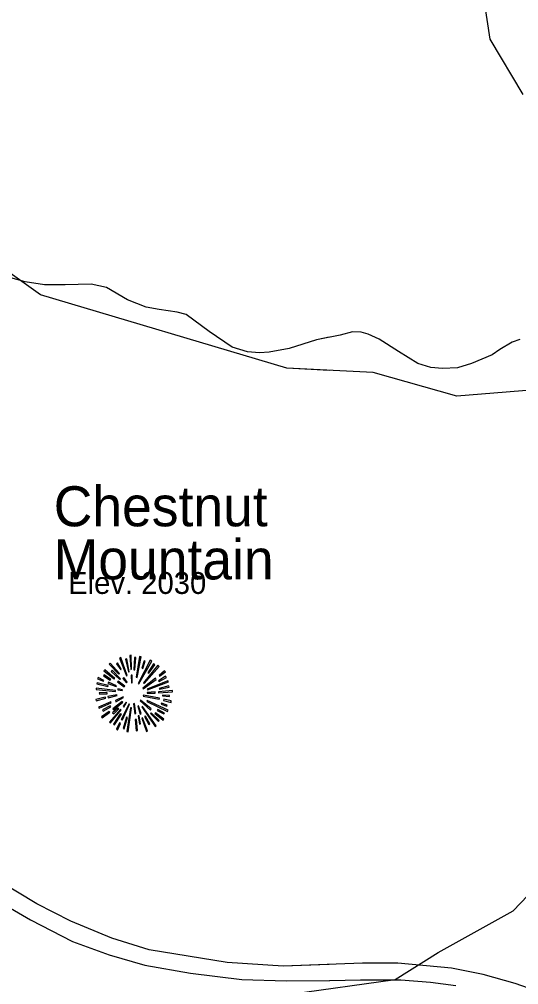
# Model space of a CAD drawing. Extents: x 990631 to 1056237, y 535999 to 585651.
# Drawn here: x 1020086 to 1021960, y 561988 to 565608 of the extents above; entities that cross this region are included whole.
import ezdxf

# ---------------------------------------------------------------- set-up
doc = ezdxf.new("R2010")
doc.units = 0
for name, color, linetype in [('Exist Geographical Mountain Summit CELL', 7, 'Continuous'), ('Exist Geographical Mountain Summit Label', 7, 'Continuous'), ('Exist Hydrographic Creek Single Shore', 7, 'Continuous'), ('Exist Road Non-System Type 51', 7, 'Continuous'), ('Exist Road Primary Interstate Divided Center Attributed', 7, 'Continuous'), ('Exist Survey Geodetic Marker Label', 7, 'Continuous')]:
    doc.layers.add(name, color=color, linetype=linetype)

msp = doc.modelspace()

# ---------------------------------------------------------------- linework, layer by layer
at = {"layer": 'Exist Geographical Mountain Summit CELL'}
for points in [[(1020461.6, 563213), (1020487.8, 563146.1), (1020490.8, 563147.1), (1020466.8, 563215.5)], [(1020500.2, 563222.4), (1020504.2, 563170.4), (1020507.5, 563170.8), (1020506.1, 563223.5)], [(1020516.2, 563168.3), (1020520.1, 563168.3), (1020523.8, 563215.5), (1020518.3, 563215.5)], [(1020528.2, 563139.9), (1020543.1, 563217), (1020537.6, 563218.8), (1020524.9, 563140.7)], [(1020423.1, 563189.7), (1020459.1, 563152.3), (1020462.4, 563154.8), (1020427.2, 563194.4)], [(1020450.7, 563191.2), (1020466.4, 563169.4), (1020468.2, 563170.8), (1020454.8, 563195.2)], [(1020495.5, 563161), (1020498, 563161.7), (1020488.9, 563209.7), (1020484.6, 563208.6)], [(1020531.4, 563118.1), (1020534.4, 563116.3), (1020583, 563200.9), (1020577.6, 563204.6)], [(1020545.9, 563175.1), (1020549.3, 563174), (1020558.7, 563200.9), (1020554, 563202.7)], [(1020552.5, 563119.6), (1020554.7, 563117.4), (1020610.3, 563181.7), (1020606.3, 563186.4)], [(1020590, 563191.2), (1020568.9, 563157.7), (1020571.8, 563156.6), (1020594.3, 563187.9)], [(1020379.9, 563135.2), (1020402.4, 563126.5), (1020403.5, 563129.4), (1020381.4, 563140.3)], [(1020401.7, 563146.1), (1020427.5, 563129.7), (1020429.7, 563132.3), (1020404.6, 563150.1)], [(1020402.8, 563165), (1020442.4, 563134.5), (1020444.6, 563136.7), (1020406.4, 563169.4)], [(1020431.1, 563162), (1020463.8, 563133), (1020466, 563135.2), (1020434, 563167.2)], [(1020474.4, 563136.7), (1020488.2, 563120.2), (1020490.4, 563122.4), (1020477.7, 563139.6)], [(1020505.7, 563149), (1020507.1, 563119.9), (1020509.7, 563120.2), (1020509.7, 563149.4)], [(1020610.3, 563124.7), (1020637.9, 563139.6), (1020635, 563144.6), (1020608.9, 563127.2)], [(1020610.3, 563147.5), (1020612.1, 563145), (1020635, 563161.3), (1020631.4, 563165)], [(1020377, 563115.9), (1020418.4, 563106.5), (1020419.5, 563109.7), (1020378.1, 563120.6)], [(1020418.4, 563118.1), (1020448.9, 563106.1), (1020450.1, 563108.3), (1020420.6, 563122.2)], [(1020454.8, 563123.6), (1020479.9, 563104.6), (1020482, 563107.5), (1020457.3, 563126.8)], [(1020549.3, 563099.6), (1020551.1, 563097), (1020599.7, 563133), (1020596.5, 563137.4)], [(1020566.3, 563096.7), (1020567.4, 563094.4), (1020645.5, 563123.2), (1020643.7, 563127.9)], [(1020612.1, 563096.7), (1020648.9, 563103.2), (1020647.4, 563108.7), (1020610.7, 563098.9)], [(1020374.4, 563094.8), (1020446.4, 563087.9), (1020446.7, 563090.8), (1020374.4, 563099.9)], [(1020386.5, 563077.4), (1020416.2, 563078.9), (1020416.2, 563082.5), (1020385.4, 563082.5)], [(1020418.8, 563068.4), (1020419.9, 563063.6), (1020453, 563072), (1020452.3, 563075.6)], [(1020446.4, 563054.2), (1020448.6, 563049.4), (1020477.3, 563064.6), (1020476.3, 563068)], [(1020455.1, 563093.8), (1020472.2, 563091.6), (1020472.6, 563093.8), (1020455.9, 563098.1)], [(1020550.7, 563070.2), (1020611.4, 563058.2), (1020612.5, 563062.5), (1020551.8, 563073.8)], [(1020565.3, 563084), (1020565.3, 563081.1), (1020595.4, 563081.1), (1020596.1, 563086.1)], [(1020608.5, 563082.9), (1020660.8, 563086.1), (1020661.2, 563090.8), (1020608.9, 563086.1)], [(1020623.4, 563070.9), (1020649.9, 563068.7), (1020649.9, 563073), (1020623.8, 563074.1)], [(1020373, 563057.1), (1020374.4, 563052), (1020410.5, 563062.5), (1020408.3, 563065.8)], [(1020382.8, 563029.4), (1020385.4, 563024.8), (1020430.8, 563044.7), (1020429.3, 563049.4)], [(1020400.3, 563013.5), (1020429.3, 563030.2), (1020427.2, 563033.8), (1020398.1, 563018.5)], [(1020436.6, 563022.9), (1020439.5, 563019.2), (1020474, 563047.6), (1020472.2, 563050.1)], [(1020468.2, 562982.9), (1020472.6, 562981.1), (1020499.1, 563039.6), (1020496.6, 563040.4)], [(1020475.1, 563032.3), (1020478.4, 563029.4), (1020488.5, 563045.8), (1020486.7, 563047.2)], [(1020515.1, 563041.5), (1020519.1, 563004.4), (1020523.5, 563004.7), (1020518.3, 563042.2)], [(1020531.1, 563032.7), (1020539.8, 563002.9), (1020543.8, 563004.7), (1020533.2, 563033.8)], [(1020539.5, 563053.1), (1020578, 563017.8), (1020580.5, 563022.2), (1020541.3, 563055.3)], [(1020545.6, 563030.5), (1020596.1, 562955.7), (1020599.7, 562958.6), (1020548.1, 563031.6)], [(1020564.5, 563050.6), (1020642.7, 563012.3), (1020644.5, 563017.8), (1020566, 563053.4)], [(1020617.9, 563040.4), (1020639, 563032.3), (1020640.8, 563036.7), (1020619.4, 563043.6)], [(1020627.4, 563053.8), (1020655.7, 563046.5), (1020656.4, 563052), (1020628.4, 563058.2)], [(1020394.1, 562992.7), (1020397, 562988.7), (1020425.4, 563009.8), (1020422.7, 563013.1)], [(1020425, 562973.1), (1020427.9, 562970.6), (1020468.6, 563018.2), (1020465.7, 563020.3)], [(1020440.3, 563004.4), (1020459.5, 563022.5), (1020456.2, 563024.8), (1020435.8, 563007.6)], [(1020465, 563004.4), (1020439.9, 562965.1), (1020443.1, 562962.6), (1020469, 563002.2)], [(1020489.6, 562937.5), (1020494.4, 562936.4), (1020507.1, 563025.8), (1020503.8, 563026.6)], [(1020540.9, 562966.2), (1020535.4, 562996), (1020532.2, 562996), (1020536.6, 562965.1)], [(1020556.1, 562993.4), (1020572.1, 562964), (1020576.2, 562966.2), (1020559.8, 562994.9)], [(1020578, 563004.7), (1020608.1, 562975.6), (1020611.4, 562978.2), (1020580.2, 563007.2)], [(1020594.7, 563005.4), (1020625.2, 562979.6), (1020628.4, 562983.3), (1020596.5, 563008)], [(1020603.8, 563016.4), (1020628.8, 563003.3), (1020631.4, 563006.9), (1020606, 563020.3)], [(1020450.1, 562945.9), (1020454.8, 562943), (1020465.7, 562967.6), (1020462.4, 562969.9)], [(1020479.9, 562947.7), (1020491.8, 562990.5), (1020488.2, 562990.9), (1020475.5, 562948.7)], [(1020521.3, 562982.9), (1020524.9, 562940.5), (1020528.9, 562941.5), (1020525.6, 562982.9)], [(1020545.6, 562987.7), (1020563.1, 562937.9), (1020567.4, 562939.7), (1020548.5, 562988.4)]]:
    msp.add_lwpolyline(points, close=True, dxfattribs=at)
at = {"layer": 'Exist Hydrographic Creek Single Shore'}
for points in [[(1021249.1, 564291.9), (1021089.6, 564300), (1020164.9, 564574.6), (1020042.6, 564662.4), (1019938.8, 564799.1), (1019766.4, 564878), (1019451, 564923.8), (1019312.9, 565034.9), (1019245.3, 565256.1), (1019174.5, 565382.3)], [(1022431.1, 563514.8), (1022258.1, 563836.6), (1022232.3, 564053.8), (1022186.8, 564189.2), (1022112.9, 564226.8), (1021728.3, 564195.2), (1021414.4, 564283.6), (1021089.6, 564300), (1020164.9, 564574.6), (1020042.6, 564662.4), (1019938.8, 564799.1), (1019766.4, 564878), (1019451, 564923.8), (1019312.9, 565034.9), (1019245.3, 565256.1), (1019174.5, 565382.3)], [(1021657.7, 562109.2), (1021939, 562264.4), (1022129.1, 562464.1), (1022341.3, 562574.6), (1022478.8, 562703.2), (1022535.1, 562885.8), (1022502.3, 563152.3), (1022435.1, 563390), (1022431.1, 563514.8)], [(1021421.8, 559650), (1021225.3, 559708.5), (1021036.9, 559847.4), (1020643.1, 560042.4), (1020579.7, 560283.3), (1020545, 560494), (1020518.2, 560698.1), (1020521.6, 560796.4), (1020649.1, 561125.4), (1020689.8, 561593.8), (1020761.1, 561730.2), (1020958.5, 561900.2), (1021102.2, 561953.1), (1021495.9, 562007.5), (1021657.7, 562109.2)]]:
    msp.add_lwpolyline(points, dxfattribs=at)
at = {"layer": 'Exist Road Non-System Type 51'}
for points in [[(1022008.3, 566910.7), (1021909.2, 566753.7), (1021900.9, 566563.7), (1021810.1, 566390.2), (1021669.7, 566233.2), (1021686.2, 566158.8), (1021818.3, 565756.4), (1021851.4, 565533.3), (1021975.3, 565326.7)], [(1021249.1, 564415.8), (1021201.7, 564406.7), (1021098.4, 564374.2), (1021024, 564360.7), (1020987.9, 564357.8), (1020941.9, 564361.3), (1020884.5, 564379.3), (1020798.4, 564438.2), (1020712.5, 564501.2), (1020678.9, 564510.3), (1020611, 564520.5), (1020561.4, 564528.3), (1020492.1, 564556.5), (1020413.6, 564603.1), (1020356.1, 564615), (1020258, 564612.4), (1020180, 564613), (1020108.2, 564623.4), (1020054.7, 564639.1)], [(1021964.2, 564407.3), (1021936, 564398.1), (1021889, 564369.6), (1021860.2, 564350.6), (1021783.1, 564317.2), (1021730.6, 564301), (1021674.3, 564298.9), (1021630.6, 564302.2), (1021581.1, 564318), (1021508.3, 564362.5), (1021435.8, 564409), (1021394.6, 564428.2), (1021368.8, 564435.1), (1021336.8, 564436.2), (1021290.3, 564423.7), (1021201.7, 564406.7), (1021098.4, 564374.2), (1021024, 564360.7), (1020987.9, 564357.8), (1020941.9, 564361.3), (1020884.5, 564379.3), (1020798.4, 564438.2), (1020712.5, 564501.2), (1020678.9, 564510.3), (1020611, 564520.5), (1020561.4, 564528.3), (1020492.1, 564556.5), (1020413.6, 564603.1), (1020356.1, 564615), (1020258, 564612.4), (1020180, 564613), (1020108.2, 564623.4), (1020054.7, 564639.1)]]:
    msp.add_lwpolyline(points, dxfattribs=at)
at = {"layer": 'Exist Road Primary Interstate Divided Center Attributed'}
for points in [[(1021249.1, 562063.8), (1021075.9, 562057.6), (1020865.6, 562071), (1020573.6, 562119.2), (1020432.9, 562162.1), (1020278.9, 562226.5), (1020151.6, 562290.8), (1019998.9, 562381.9), (1019605.1, 562635.2), (1019318.5, 562825.5), (1018970.2, 563064), (1018711.7, 563220.8), (1018589.8, 563279.7), (1018481.3, 563318.6), (1018296.5, 563370.9), (1018103.6, 563405.7), (1017977.7, 563420.4), (1017792.8, 563424.5), (1017632.1, 563417.8)], [(1022167.6, 561915.6), (1021946.6, 561991.9), (1021826, 562026.8), (1021708.1, 562049.6), (1021505.9, 562068.3), (1021373.3, 562068.3), (1021075.9, 562057.6), (1020865.6, 562071), (1020573.6, 562119.2), (1020432.9, 562162.1), (1020278.9, 562226.5), (1020151.6, 562290.8), (1019998.9, 562381.9), (1019605.1, 562635.2), (1019318.5, 562825.5), (1018970.2, 563064), (1018711.7, 563220.8), (1018589.8, 563279.7), (1018481.3, 563318.6), (1018296.5, 563370.9), (1018103.6, 563405.7), (1017977.7, 563420.4), (1017792.8, 563424.5), (1017632.1, 563417.8)], [(1017622.7, 563358.8), (1017721.8, 563364.2), (1017926.8, 563364.2), (1018050, 563358.8), (1018201.3, 563336), (1018362.1, 563299.8), (1018508.1, 563246.2), (1018662.1, 563183.3), (1018919.3, 563029.1), (1019287.7, 562781.2), (1019564.9, 562596.3), (1019699.1, 562503.1), (1019968.1, 562324.3), (1020127.5, 562231.8), (1020285.6, 562150.1), (1020423.6, 562100.5), (1020557.5, 562061.6), (1020729, 562030.8), (1020920.5, 562008), (1021087.9, 562002.7), (1021249.1, 562004)], [(1019968.1, 562324.3), (1020127.5, 562231.8), (1020285.6, 562150.1), (1020423.6, 562100.5), (1020557.5, 562061.6), (1020729, 562030.8), (1020920.5, 562008), (1021087.9, 562002.7), (1021251.4, 562004), (1021366.6, 562006.7), (1021517.9, 562006.7), (1021629.1, 561997.3), (1021724.2, 561985.2)]]:
    msp.add_lwpolyline(points, dxfattribs=at)

# ---------------------------------------------------------------- texts
at = {"layer": 'Exist Geographical Mountain Summit Label'}
for s, p in [('Chestnut', (1020215.2, 563707.1)), ('Chestnut', (1020215.2, 563707.1)), ('Mountain', (1020215.2, 563507.9)), ('Mountain', (1020215.2, 563507.9))]:
    msp.add_text(s, height=150, dxfattribs=at).set_placement(p)
at = {"layer": 'Exist Survey Geodetic Marker Label'}
msp.add_text('Elev. 2030', height=82.02, dxfattribs=at).set_placement((1020269.2, 563453.4))

doc.saveas('drawing.dxf')
